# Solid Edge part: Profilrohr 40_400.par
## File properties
Username: ahadarics
Dokumentum tartalom típus: 0
Author: ahadarics
Last saved by: ahadarics
Revision: 86
Sűrűség: 0,000 kg/m^3
Pontosság: 0,990
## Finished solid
Body 1: solid body, 175 faces, 519 edges, 346 vertices.
  Faces by surface: cylinder 107, plane 68
  Edges by curve: line 305, circle 214
Bounding box of the edges (mm): 51.354 x 51.354 x 443.000, from (-25.6768, -25.6768, -14) to (25.6768, 25.6768, 429).
Cylindrical faces by radius (mm): R0.1 x16, R0.2 x30, R0.5 x28, R1 x8, R2.7 x8, R3.5 x4, R5 x4, R20 x1, R22 x8
Planar faces by outward normal: +x 6, +y 6, +z 1, -x 4, -y 4, -z 1, oblique 46
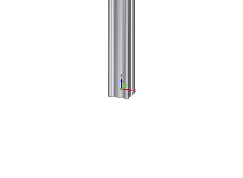
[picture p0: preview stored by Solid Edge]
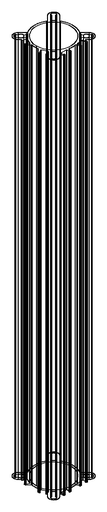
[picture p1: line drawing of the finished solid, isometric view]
